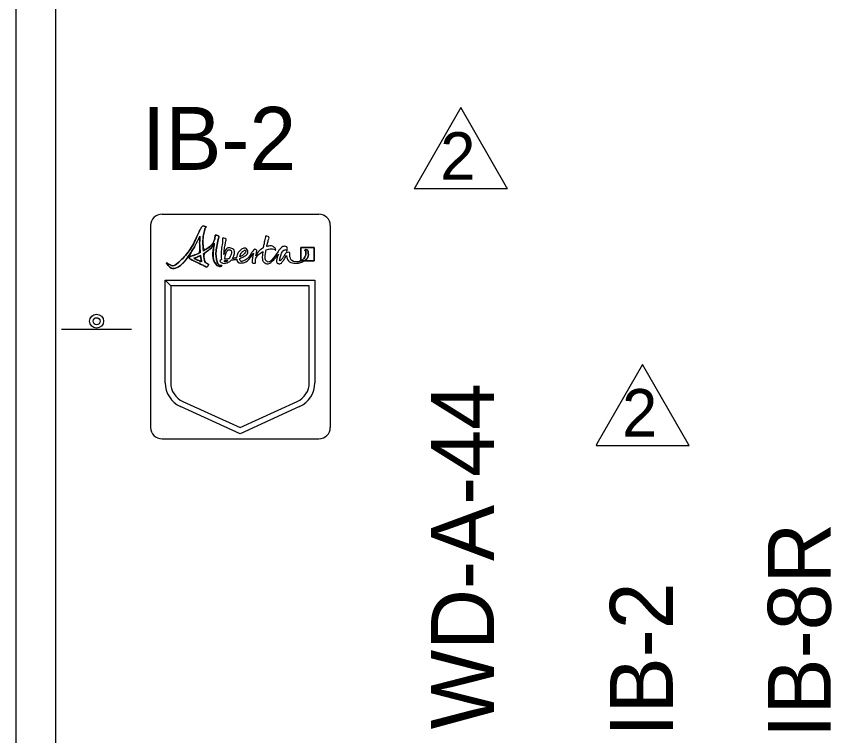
# Model space of a CAD drawing. Extents: x 1806 to 2022, y 110 to 389.
# Drawn here: x 1888.6 to 1913.47, y 300.26 to 322.2 of the extents above; entities that cross this region are included whole.
import ezdxf

# ---------------------------------------------------------------- set-up
doc = ezdxf.new("R2010")
doc.units = 0
for name, color, linetype in [('Level 10', 7, 'Continuous'), ('Level 2', 7, 'Continuous'), ('Level 44', 7, 'Continuous'), ('Level 50', 7, 'Continuous'), ('Level 53', 7, 'Continuous'), ('Level 60', 7, 'Continuous')]:
    doc.layers.add(name, color=color, linetype=linetype)

msp = doc.modelspace()

# ---------------------------------------------------------------- linework, layer by layer
at = {"layer": 'Level 10'}
for p, q in [((1888.603, 296.177), (1888.603, 355.206)), ((1889.812, 296.293), (1889.812, 355.206))]:
    msp.add_line(p, q, dxfattribs=at)
at = {"layer": 'Level 2'}
for p, q in [((1893.047, 316.16), (1897.832, 316.16)), ((1893.047, 316.16), (1897.832, 316.16)), ((1892.7, 315.813), (1892.7, 309.658)), ((1898.179, 315.813), (1898.179, 309.658)), ((1893.143, 311.02), (1893.143, 314.147)), ((1893.143, 314.147), (1893.314, 313.976)), ((1893.314, 313.976), (1893.143, 314.147)), ((1893.143, 314.147), (1897.708, 314.147)), ((1897.708, 314.147), (1897.708, 311.02)), ((1893.314, 313.976), (1893.314, 311.02)), ((1897.537, 313.976), (1893.314, 313.976)), ((1897.537, 311.02), (1897.537, 313.976)), ((1893.682, 310.449), (1895.426, 309.656)), ((1895.426, 309.656), (1897.169, 310.449)), ((1895.426, 309.467), (1893.611, 310.293)), ((1897.24, 310.293), (1895.426, 309.467)), ((1893.047, 309.311), (1897.832, 309.311))]:
    msp.add_line(p, q, dxfattribs=at)
for centre, radius, start, end in [((1893.047, 315.813), 0.347, 90, 180), ((1897.832, 315.813), 0.347, 0, 90), ((1893.942, 311.02), 0.799, 180, 245.5432), ((1893.942, 311.02), 0.628, 180, 245.5432), ((1896.909, 311.02), 0.628, 294.4568, 0), ((1896.909, 311.02), 0.799, 294.4568, 0), ((1893.047, 309.658), 0.347, 180, 270), ((1897.832, 309.658), 0.347, 270, 0)]:
    msp.add_arc(centre, radius, start, end, dxfattribs=at)
at = {"layer": 'Level 44'}
msp.add_line((1889.981, 312.659), (1892.115, 312.659), dxfattribs=at)
for radius in [0.213, 0.107]:
    msp.add_circle((1891.052, 312.898), radius, dxfattribs=at)
at = {"layer": 'Level 53'}
msp.add_line((1897.388, 314.743), (1897.288, 314.743), dxfattribs=at)
msp.add_lwpolyline([(1897.388, 314.743), (1897.684, 314.743), (1897.684, 315.15), (1897.276, 315.15), (1897.276, 314.743), (1897.288, 314.743)], dxfattribs=at)
for points, degree in [([(1894.834, 314.595), (1894.791, 314.601), (1894.733, 314.661), (1894.716, 314.759), (1894.685, 314.936), (1894.703, 315.11), (1894.755, 315.369), (1894.765, 315.418), (1894.798, 315.504), (1894.692, 315.52), (1894.658, 315.525), (1894.675, 315.508), (1894.666, 315.464), (1894.625, 315.27), (1894.467, 315.131), (1894.308, 315.038), (1894.291, 315.259), (1894.298, 315.505), (1894.34, 315.655), (1894.375, 315.782), (1894.417, 315.759), (1894.365, 315.786), (1894.31, 315.814), (1894.252, 315.777), (1894.204, 315.682), (1894.157, 315.587), (1893.938, 315.073), (1893.589, 314.726), (1893.411, 314.548), (1893.249, 314.64), (1893.217, 314.667), (1893.19, 314.689), (1893.181, 314.655), (1893.213, 314.62), (1893.358, 314.464), (1893.569, 314.553), (1893.646, 314.63), (1893.858, 314.843), (1894.105, 315.3), (1894.205, 315.493), (1894.196, 315.384), (1894.193, 315.201), (1894.213, 314.987), (1894.105, 314.934), (1894.008, 314.903), (1893.962, 314.891), (1893.913, 314.878), (1893.882, 314.858), (1893.881, 314.835), (1893.88, 314.81), (1893.913, 314.789), (1893.962, 314.766), (1894.047, 314.725), (1894.298, 314.607), (1894.359, 314.571), (1894.412, 314.54), (1894.438, 314.564), (1894.454, 314.597), (1894.474, 314.64), (1894.418, 314.665), (1894.364, 314.682), (1894.343, 314.754), (1894.326, 314.852), (1894.315, 314.96), (1894.442, 315.038), (1894.568, 315.143), (1894.64, 315.273), (1894.622, 315.164), (1894.575, 314.793), (1894.692, 314.636), (1894.718, 314.602), (1894.775, 314.564), (1894.831, 314.57), (1894.857, 314.572), (1894.87, 314.589), (1894.867, 314.595), (1894.865, 314.6), (1894.85, 314.593), (1894.834, 314.595)], 3), ([(1894.308, 315.038), (1894.291, 315.259), (1894.298, 315.505), (1894.34, 315.655), (1894.375, 315.782), (1894.417, 315.759), (1894.365, 315.786), (1894.31, 315.814), (1894.252, 315.777), (1894.204, 315.682), (1894.157, 315.587), (1893.938, 315.073), (1893.589, 314.726), (1893.411, 314.548), (1893.249, 314.64), (1893.217, 314.667), (1893.19, 314.689), (1893.181, 314.655), (1893.213, 314.62), (1893.358, 314.464), (1893.569, 314.553), (1893.646, 314.63), (1893.858, 314.843), (1894.105, 315.3), (1894.205, 315.493)], 3), ([(1894.205, 315.493), (1894.196, 315.384), (1894.193, 315.201), (1894.213, 314.987)], 2), ([(1894.834, 314.595), (1894.791, 314.601), (1894.733, 314.661), (1894.716, 314.759), (1894.685, 314.936), (1894.703, 315.11), (1894.755, 315.369), (1894.765, 315.418), (1894.798, 315.504), (1894.692, 315.52), (1894.658, 315.525), (1894.675, 315.508), (1894.666, 315.464), (1894.625, 315.27), (1894.467, 315.131), (1894.308, 315.038)], 3), ([(1894.932, 314.931), (1894.941, 315.035), (1894.957, 315.162), (1894.981, 315.279), (1894.991, 315.328), (1895.024, 315.413), (1894.918, 315.43), (1894.884, 315.435), (1894.889, 315.419), (1894.892, 315.373), (1894.896, 315.312), (1894.827, 314.939), (1894.863, 314.776)], 3), ([(1896.239, 315.176), (1896.251, 315.23), (1896.265, 315.286), (1896.28, 315.339), (1896.293, 315.388), (1896.334, 315.474), (1896.228, 315.49), (1896.195, 315.495), (1896.209, 315.479), (1896.198, 315.434), (1896.178, 315.35), (1896.152, 315.242), (1896.133, 315.133)], 3), ([(1894.315, 314.96), (1894.442, 315.038), (1894.568, 315.143), (1894.64, 315.273)], 2), ([(1894.64, 315.273), (1894.622, 315.164), (1894.575, 314.793), (1894.692, 314.636), (1894.718, 314.602), (1894.775, 314.564), (1894.831, 314.57), (1894.857, 314.572), (1894.87, 314.589), (1894.867, 314.595), (1894.865, 314.6), (1894.85, 314.593), (1894.834, 314.595)], 3), ([(1895.195, 314.81), (1895.271, 314.933), (1895.264, 315.1), (1895.153, 315.127), (1895.025, 315.16), (1894.96, 315.035), (1894.932, 314.931)], 3), ([(1894.96, 314.787), (1894.977, 314.918), (1895.045, 315.099), (1895.13, 315.07), (1895.179, 315.053), (1895.153, 314.9), (1895.09, 314.798)], 3), ([(1895.419, 314.815), (1895.436, 314.82), (1895.452, 314.826), (1895.465, 314.831), (1895.627, 314.903), (1895.682, 315.011), (1895.641, 315.076), (1895.602, 315.139), (1895.491, 315.12), (1895.403, 315.027), (1895.36, 314.982), (1895.327, 314.903), (1895.323, 314.832)], 3), ([(1895.907, 314.89), (1895.918, 314.941), (1895.933, 314.997), (1895.935, 315.034), (1895.936, 315.074), (1895.908, 315.083), (1895.898, 315.086), (1895.875, 315.093), (1895.847, 315.081), (1895.819, 315.042), (1895.755, 314.951), (1895.673, 314.808), (1895.549, 314.747), (1895.46, 314.704), (1895.421, 314.748), (1895.419, 314.815)], 3), ([(1896.133, 315.133), (1896.047, 315.083), (1895.966, 315), (1895.907, 314.89)], 2), ([(1897.162, 314.707), (1896.995, 314.707), (1896.952, 314.837), (1896.944, 314.901), (1896.938, 314.944), (1896.948, 315.005), (1896.874, 314.997), (1896.822, 314.991), (1896.775, 314.891), (1896.71, 314.806), (1896.653, 314.733), (1896.628, 314.74), (1896.641, 314.803), (1896.658, 314.881), (1896.723, 315.065), (1896.798, 315.078), (1896.832, 315.084), (1896.845, 315.023), (1896.86, 315.061), (1896.876, 315.099), (1896.862, 315.182), (1896.784, 315.182), (1896.73, 315.182), (1896.665, 315.124), (1896.612, 315.059), (1896.566, 315.002), (1896.331, 314.656), (1896.232, 314.731), (1896.186, 314.766), (1896.19, 314.908), (1896.219, 315.075)], 3), ([(1896.219, 315.075), (1896.336, 315.12), (1896.433, 315.105), (1896.488, 315.079), (1896.515, 315.066), (1896.519, 315.068), (1896.507, 315.098), (1896.49, 315.142), (1896.396, 315.21), (1896.249, 315.179), (1896.246, 315.178), (1896.242, 315.177), (1896.239, 315.176)], 3), ([(1897.276, 315.15), (1897.276, 315.15), (1897.276, 314.743), (1897.276, 314.743), (1897.276, 314.743), (1897.288, 314.743), (1897.288, 314.743), (1897.376, 314.796), (1897.436, 314.897), (1897.436, 314.98), (1897.436, 315.052), (1897.398, 315.048), (1897.402, 315.059), (1897.414, 315.087), (1897.504, 315.071), (1897.509, 314.969), (1897.514, 314.883), (1897.469, 314.8), (1897.388, 314.743), (1897.388, 314.743), (1897.684, 314.743), (1897.684, 314.743), (1897.684, 314.743), (1897.684, 315.15), (1897.684, 315.15), (1897.684, 315.15), (1897.276, 315.15), (1897.276, 315.15)], 3), ([(1897.288, 314.743), (1897.376, 314.796), (1897.436, 314.897), (1897.436, 314.98), (1897.436, 315.052), (1897.398, 315.048), (1897.402, 315.059), (1897.414, 315.087), (1897.504, 315.071), (1897.509, 314.969), (1897.514, 314.883), (1897.469, 314.8), (1897.388, 314.743)], 3), ([(1894.213, 314.987), (1894.105, 314.934), (1894.008, 314.903), (1893.962, 314.891), (1893.913, 314.878), (1893.882, 314.858), (1893.881, 314.835), (1893.88, 314.81), (1893.913, 314.789), (1893.962, 314.766), (1894.047, 314.725), (1894.298, 314.607), (1894.359, 314.571), (1894.412, 314.54), (1894.438, 314.564), (1894.454, 314.597), (1894.474, 314.64), (1894.418, 314.665), (1894.364, 314.682)], 3), ([(1894.018, 314.816), (1894.074, 314.837), (1894.146, 314.867), (1894.221, 314.907)], 2), ([(1894.018, 314.816), (1894.074, 314.837), (1894.146, 314.867), (1894.221, 314.907), (1894.232, 314.82), (1894.243, 314.758), (1894.255, 314.711), (1894.2, 314.731), (1894.121, 314.764), (1894.018, 314.816)], 3), ([(1894.221, 314.907), (1894.232, 314.82), (1894.243, 314.758), (1894.255, 314.711)], 2), ([(1894.364, 314.682), (1894.343, 314.754), (1894.326, 314.852), (1894.315, 314.96)], 2), ([(1895.323, 314.832), (1895.286, 314.824), (1895.243, 314.817), (1895.195, 314.81)], 2), ([(1895.324, 314.792), (1895.333, 314.72), (1895.38, 314.665), (1895.488, 314.675), (1895.643, 314.69), (1895.78, 314.879), (1895.832, 314.971)], 3), ([(1895.505, 315.019), (1895.559, 315.069), (1895.586, 315.066), (1895.593, 315.052), (1895.608, 315.023), (1895.545, 314.92), (1895.423, 314.864)], 3), ([(1895.423, 314.864), (1895.433, 314.919), (1895.463, 314.98), (1895.505, 315.019)], 2), ([(1895.832, 314.971), (1895.823, 314.873), (1895.759, 314.659), (1895.868, 314.67), (1895.91, 314.674), (1895.892, 314.681), (1895.894, 314.718), (1895.904, 314.847), (1896.011, 314.956), (1896.117, 315.023)], 3), ([(1896.117, 315.023), (1896.099, 314.865), (1896.105, 314.724), (1896.177, 314.679), (1896.309, 314.597), (1896.496, 314.814), (1896.599, 314.947)], 3), ([(1896.599, 314.947), (1896.546, 314.829), (1896.517, 314.678), (1896.595, 314.655), (1896.687, 314.628), (1896.76, 314.78), (1896.845, 314.898)], 3), ([(1896.845, 314.898), (1896.855, 314.814), (1896.911, 314.669), (1897.137, 314.669), (1897.238, 314.669), (1897.325, 314.697), (1897.388, 314.743)], 3), ([(1894.255, 314.711), (1894.2, 314.731), (1894.121, 314.764), (1894.018, 314.816)], 2), ([(1894.863, 314.776), (1894.817, 314.761), (1894.799, 314.726), (1894.858, 314.69), (1894.898, 314.665), (1894.988, 314.656), (1895.078, 314.701), (1895.111, 314.717), (1895.139, 314.739), (1895.162, 314.766)], 3), ([(1894.946, 314.708), (1894.952, 314.713), (1894.956, 314.72), (1894.956, 314.729), (1894.956, 314.735), (1894.956, 314.74), (1894.956, 314.746)], 3), ([(1894.983, 314.708), (1894.968, 314.706), (1894.956, 314.706), (1894.946, 314.708)], 2), ([(1894.956, 314.746), (1894.979, 314.747), (1895.015, 314.75), (1895.058, 314.754)], 2), ([(1895.09, 314.798), (1895.049, 314.794), (1895.006, 314.79), (1894.96, 314.787)], 2), ([(1895.058, 314.754), (1895.035, 314.73), (1895.01, 314.712), (1894.983, 314.708)], 2), ([(1895.162, 314.766), (1895.216, 314.773), (1895.272, 314.781), (1895.324, 314.792)], 2), ([(1897.288, 314.743), (1897.25, 314.72), (1897.208, 314.707), (1897.162, 314.707)], 2)]:
    msp.add_open_spline(points, degree=degree, dxfattribs=at)
at = {"layer": 'Level 60'}
for points in [[(1902.159, 319.415), (1900.766, 316.99)], [(1903.553, 316.99), (1902.159, 319.415)], [(1900.766, 316.99), (1900.74, 316.945), (1903.579, 316.945), (1903.553, 316.99)], [(1907.704, 311.581), (1906.311, 309.156)], [(1909.098, 309.156), (1907.704, 311.581)], [(1906.311, 309.156), (1906.285, 309.111), (1909.124, 309.111), (1909.098, 309.156)]]:
    msp.add_lwpolyline(points, dxfattribs=at)

# ---------------------------------------------------------------- texts
at = {"layer": 'Level 50'}
for s, rotation, p in [('IB-2', 360, (1892.433, 317.513)), ('WD-A-44', 90, (1903.172, 300.452)), ('IB-8R', 90, (1913.444, 300.186)), ('IB-2', 90, (1908.627, 300.222))]:
    msp.add_text(s, height=1.9199, rotation=rotation, dxfattribs=at).set_placement(p)
at = {"layer": 'Level 60'}
for p in [(1901.532, 317.214), (1907.077, 309.38)]:
    msp.add_text('2', height=1.448, rotation=360, dxfattribs=at).set_placement(p)

doc.saveas('drawing.dxf')
